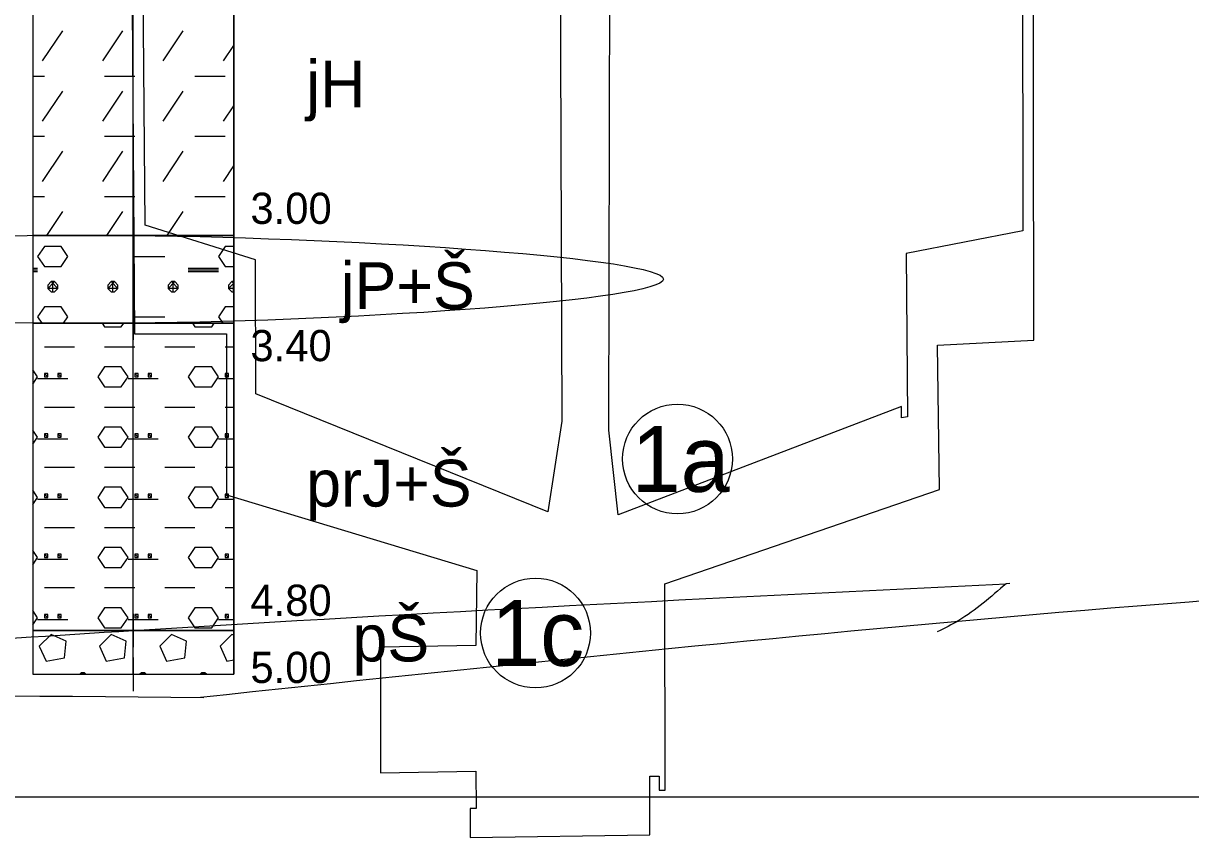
# Model space of a CAD drawing. Extents: x 3042 to 4120, y 576 to 2694.
# Drawn here: x 3468.92 to 3495.5, y 742.77 to 761.32 of the extents above; entities that cross this region are included whole.
import ezdxf

# ---------------------------------------------------------------- set-up
doc = ezdxf.new("R2010")
doc.units = 0
for name, color, linetype in [('18', 7, 'Continuous'), ('51', 7, 'Continuous'), ('52', 7, 'Continuous'), ('53', 7, 'Continuous'), ('56', 7, 'Continuous'), ('nádrže', 7, 'Continuous'), ('rozhraní', 7, 'Continuous')]:
    doc.layers.add(name, color=color, linetype=linetype)

msp = doc.modelspace()

# ---------------------------------------------------------------- linework, layer by layer
at = {"layer": '18'}
for p, q in [((3471.427, 746.491), (3471.427, 771.491)), ((3471.427, 746.872), (3471.427, 746.11)), ((3471.046, 746.491), (3471.808, 746.491))]:
    msp.add_line(p, q, dxfattribs=at)
at = {"layer": '51'}
for p, q in [((3469.363, 760.467), (3469.821, 761.153)), ((3470.735, 760.467), (3471.192, 761.153)), ((3472.107, 760.467), (3472.564, 761.153)), ((3473.478, 760.467), (3473.713, 760.819)), ((3469.141, 760.124), (3469.402, 760.124)), ((3470.773, 760.124), (3471.459, 760.124)), ((3472.831, 760.124), (3473.516, 760.124)), ((3469.363, 759.096), (3469.821, 759.782)), ((3470.735, 759.096), (3471.192, 759.782)), ((3472.107, 759.096), (3472.564, 759.782)), ((3473.478, 759.096), (3473.713, 759.447)), ((3469.141, 758.753), (3469.402, 758.753)), ((3470.773, 758.753), (3471.459, 758.753)), ((3472.831, 758.753), (3473.516, 758.753)), ((3469.363, 757.724), (3469.821, 758.41)), ((3470.735, 757.724), (3471.192, 758.41)), ((3472.107, 757.724), (3472.564, 758.41)), ((3473.478, 757.724), (3473.713, 758.076)), ((3469.141, 757.381), (3469.402, 757.381)), ((3470.773, 757.381), (3471.459, 757.381)), ((3472.831, 757.381), (3473.516, 757.381)), ((3469.456, 756.491), (3469.821, 757.038)), ((3470.827, 756.491), (3471.192, 757.038)), ((3472.199, 756.491), (3472.564, 757.038)), ((3471.459, 756.01), (3472.145, 756.01)), ((3469.141, 755.743), (3469.249, 755.743)), ((3472.678, 755.743), (3473.364, 755.743)), ((3473.516, 755.781), (3473.713, 755.781)), ((3469.141, 755.705), (3469.249, 755.705)), ((3469.141, 755.667), (3469.249, 755.667)), ((3472.678, 755.705), (3473.364, 755.705)), ((3472.678, 755.667), (3473.364, 755.667)), ((3469.592, 755.21), (3469.592, 755.438)), ((3470.964, 755.21), (3470.964, 755.438)), ((3472.335, 755.21), (3472.335, 755.438)), ((3473.707, 755.21), (3473.707, 755.438)), ((3470.719, 754.491), (3470.773, 754.409)), ((3471.459, 754.638), (3472.145, 754.638)), ((3472.776, 754.491), (3472.831, 754.409)), ((3469.402, 753.952), (3470.087, 753.952)), ((3470.773, 753.952), (3471.459, 753.952)), ((3472.145, 753.952), (3472.831, 753.952)), ((3473.516, 753.952), (3473.713, 753.952)), ((3469.249, 753.228), (3469.935, 753.228)), ((3471.307, 753.228), (3471.992, 753.228)), ((3473.364, 753.228), (3473.713, 753.228)), ((3469.402, 752.581), (3470.087, 752.581)), ((3470.773, 752.581), (3471.459, 752.581)), ((3472.145, 752.581), (3472.831, 752.581)), ((3473.516, 752.581), (3473.713, 752.581)), ((3469.249, 751.857), (3469.935, 751.857)), ((3471.307, 751.857), (3471.992, 751.857)), ((3473.364, 751.857), (3473.713, 751.857)), ((3469.402, 751.209), (3470.087, 751.209)), ((3470.773, 751.209), (3471.459, 751.209)), ((3472.145, 751.209), (3472.831, 751.209)), ((3473.516, 751.209), (3473.713, 751.209)), ((3469.249, 750.485), (3469.935, 750.485)), ((3471.307, 750.485), (3471.992, 750.485)), ((3473.364, 750.485), (3473.713, 750.485)), ((3469.402, 749.837), (3470.087, 749.837)), ((3470.773, 749.837), (3471.459, 749.837)), ((3472.145, 749.837), (3472.831, 749.837)), ((3473.516, 749.837), (3473.713, 749.837)), ((3469.249, 749.114), (3469.935, 749.114)), ((3471.307, 749.114), (3471.992, 749.114)), ((3473.364, 749.114), (3473.713, 749.114)), ((3469.402, 748.466), (3470.087, 748.466)), ((3470.773, 748.466), (3471.459, 748.466)), ((3472.145, 748.466), (3472.831, 748.466)), ((3473.516, 748.466), (3473.713, 748.466)), ((3469.249, 747.742), (3469.935, 747.742)), ((3471.307, 747.742), (3471.992, 747.742)), ((3473.364, 747.742), (3473.713, 747.742)), ((3470.24, 746.523), (3470.208, 746.491)), ((3470.278, 746.491), (3470.278, 746.523)), ((3470.284, 746.491), (3470.316, 746.523)), ((3471.611, 746.523), (3471.579, 746.491)), ((3471.649, 746.491), (3471.649, 746.523)), ((3471.656, 746.491), (3471.688, 746.523)), ((3472.983, 746.523), (3472.951, 746.491)), ((3473.021, 746.491), (3473.021, 746.523)), ((3473.027, 746.491), (3473.059, 746.523))]:
    msp.add_line(p, q, dxfattribs=at)
for points in [[(3469.141, 756.491), (3473.713, 756.491), (3473.713, 762.491), (3469.141, 762.491)], [(3469.141, 754.491), (3473.713, 754.491), (3473.713, 756.491), (3469.141, 756.491)], [(3469.141, 747.491), (3473.713, 747.491), (3473.713, 754.491), (3469.141, 754.491)], [(3469.141, 746.491), (3473.713, 746.491), (3473.713, 747.491), (3469.141, 747.491)]]:
    msp.add_lwpolyline(points, close=True, dxfattribs=at)
for points in [[(3469.402, 755.781), (3469.783, 755.781), (3469.935, 756.01), (3469.783, 756.238), (3469.402, 756.238), (3469.249, 756.01), (3469.402, 755.781)], [(3473.713, 756.238), (3473.516, 756.238), (3473.364, 756.01), (3473.516, 755.781)], [(3469.554, 755.438), (3469.478, 755.362), (3469.478, 755.286), (3469.554, 755.21), (3469.63, 755.21), (3469.706, 755.286), (3469.706, 755.362), (3469.63, 755.438), (3469.554, 755.438), (3469.706, 755.286), (3469.478, 755.286), (3469.63, 755.438)], [(3470.926, 755.438), (3470.849, 755.362), (3470.849, 755.286), (3470.926, 755.21), (3471.002, 755.21), (3471.078, 755.286), (3471.078, 755.362), (3471.002, 755.438), (3470.926, 755.438), (3471.078, 755.286), (3470.849, 755.286), (3471.002, 755.438)], [(3472.297, 755.438), (3472.221, 755.362), (3472.221, 755.286), (3472.297, 755.21), (3472.373, 755.21), (3472.45, 755.286), (3472.45, 755.362), (3472.373, 755.438), (3472.297, 755.438), (3472.45, 755.286), (3472.221, 755.286), (3472.373, 755.438)], [(3473.669, 755.438), (3473.593, 755.362), (3473.593, 755.286), (3473.669, 755.21), (3473.713, 755.21)], [(3473.713, 755.286), (3473.593, 755.286), (3473.713, 755.406)], [(3473.713, 755.438), (3473.669, 755.438), (3473.713, 755.394)], [(3469.837, 754.491), (3469.935, 754.638), (3469.783, 754.867), (3469.402, 754.867), (3469.249, 754.638), (3469.347, 754.491)], [(3473.713, 754.867), (3473.516, 754.867), (3473.364, 754.638), (3473.462, 754.491)], [(3470.773, 754.409), (3471.154, 754.409), (3471.208, 754.491)], [(3472.831, 754.409), (3473.212, 754.409), (3473.266, 754.491)], [(3469.141, 753.104), (3469.249, 753.266), (3469.141, 753.429)], [(3469.402, 753.343), (3469.402, 753.266), (3469.478, 753.266), (3469.478, 753.343), (3469.402, 753.343), (3469.478, 753.266)], [(3469.706, 753.343), (3469.706, 753.266), (3469.783, 753.266), (3469.783, 753.343), (3469.706, 753.343), (3469.783, 753.266)], [(3470.773, 753.038), (3471.154, 753.038), (3471.307, 753.266), (3471.154, 753.495), (3470.773, 753.495), (3470.621, 753.266), (3470.773, 753.038)], [(3471.459, 753.343), (3471.459, 753.266), (3471.535, 753.266), (3471.535, 753.343), (3471.459, 753.343), (3471.535, 753.266)], [(3471.764, 753.343), (3471.764, 753.266), (3471.84, 753.266), (3471.84, 753.343), (3471.764, 753.343), (3471.84, 753.266)], [(3472.831, 753.038), (3473.212, 753.038), (3473.364, 753.266), (3473.212, 753.495), (3472.831, 753.495), (3472.678, 753.266), (3472.831, 753.038)], [(3473.516, 753.343), (3473.516, 753.266), (3473.593, 753.266), (3473.593, 753.343), (3473.516, 753.343), (3473.593, 753.266)], [(3469.141, 751.732), (3469.249, 751.895), (3469.141, 752.057)], [(3470.773, 751.666), (3471.154, 751.666), (3471.307, 751.895), (3471.154, 752.123), (3470.773, 752.123), (3470.621, 751.895), (3470.773, 751.666)], [(3472.831, 751.666), (3473.212, 751.666), (3473.364, 751.895), (3473.212, 752.123), (3472.831, 752.123), (3472.678, 751.895), (3472.831, 751.666)], [(3469.402, 751.971), (3469.402, 751.895), (3469.478, 751.895), (3469.478, 751.971), (3469.402, 751.971), (3469.478, 751.895)], [(3469.706, 751.971), (3469.706, 751.895), (3469.783, 751.895), (3469.783, 751.971), (3469.706, 751.971), (3469.783, 751.895)], [(3471.459, 751.971), (3471.459, 751.895), (3471.535, 751.895), (3471.535, 751.971), (3471.459, 751.971), (3471.535, 751.895)], [(3471.764, 751.971), (3471.764, 751.895), (3471.84, 751.895), (3471.84, 751.971), (3471.764, 751.971), (3471.84, 751.895)], [(3473.516, 751.971), (3473.516, 751.895), (3473.593, 751.895), (3473.593, 751.971), (3473.516, 751.971), (3473.593, 751.895)], [(3469.141, 750.361), (3469.249, 750.523), (3469.141, 750.686)], [(3470.773, 750.295), (3471.154, 750.295), (3471.307, 750.523), (3471.154, 750.752), (3470.773, 750.752), (3470.621, 750.523), (3470.773, 750.295)], [(3472.831, 750.295), (3473.212, 750.295), (3473.364, 750.523), (3473.212, 750.752), (3472.831, 750.752), (3472.678, 750.523), (3472.831, 750.295)], [(3469.402, 750.599), (3469.402, 750.523), (3469.478, 750.523), (3469.478, 750.599), (3469.402, 750.599), (3469.478, 750.523)], [(3469.706, 750.599), (3469.706, 750.523), (3469.783, 750.523), (3469.783, 750.599), (3469.706, 750.599), (3469.783, 750.523)], [(3471.459, 750.599), (3471.459, 750.523), (3471.535, 750.523), (3471.535, 750.599), (3471.459, 750.599), (3471.535, 750.523)], [(3471.764, 750.599), (3471.764, 750.523), (3471.84, 750.523), (3471.84, 750.599), (3471.764, 750.599), (3471.84, 750.523)], [(3473.516, 750.599), (3473.516, 750.523), (3473.593, 750.523), (3473.593, 750.599), (3473.516, 750.599), (3473.593, 750.523)], [(3470.773, 748.923), (3471.154, 748.923), (3471.307, 749.152), (3471.154, 749.38), (3470.773, 749.38), (3470.621, 749.152), (3470.773, 748.923)], [(3472.831, 748.923), (3473.212, 748.923), (3473.364, 749.152), (3473.212, 749.38), (3472.831, 749.38), (3472.678, 749.152), (3472.831, 748.923)], [(3469.141, 748.989), (3469.249, 749.152), (3469.141, 749.314)], [(3469.402, 749.228), (3469.402, 749.152), (3469.478, 749.152), (3469.478, 749.228), (3469.402, 749.228), (3469.478, 749.152)], [(3469.706, 749.228), (3469.706, 749.152), (3469.783, 749.152), (3469.783, 749.228), (3469.706, 749.228), (3469.783, 749.152)], [(3471.459, 749.228), (3471.459, 749.152), (3471.535, 749.152), (3471.535, 749.228), (3471.459, 749.228), (3471.535, 749.152)], [(3471.764, 749.228), (3471.764, 749.152), (3471.84, 749.152), (3471.84, 749.228), (3471.764, 749.228), (3471.84, 749.152)], [(3473.516, 749.228), (3473.516, 749.152), (3473.593, 749.152), (3473.593, 749.228), (3473.516, 749.228), (3473.593, 749.152)], [(3470.773, 747.551), (3471.154, 747.551), (3471.307, 747.78), (3471.154, 748.009), (3470.773, 748.009), (3470.621, 747.78), (3470.773, 747.551)], [(3472.831, 747.551), (3473.212, 747.551), (3473.364, 747.78), (3473.212, 748.009), (3472.831, 748.009), (3472.678, 747.78), (3472.831, 747.551)], [(3469.141, 747.617), (3469.249, 747.78), (3469.141, 747.943)], [(3469.402, 747.856), (3469.402, 747.78), (3469.478, 747.78), (3469.478, 747.856), (3469.402, 747.856), (3469.478, 747.78)], [(3469.706, 747.856), (3469.706, 747.78), (3469.783, 747.78), (3469.783, 747.856), (3469.706, 747.856), (3469.783, 747.78)], [(3471.459, 747.856), (3471.459, 747.78), (3471.535, 747.78), (3471.535, 747.856), (3471.459, 747.856), (3471.535, 747.78)], [(3471.764, 747.856), (3471.764, 747.78), (3471.84, 747.78), (3471.84, 747.856), (3471.764, 747.856), (3471.84, 747.78)], [(3473.516, 747.856), (3473.516, 747.78), (3473.593, 747.78), (3473.593, 747.856), (3473.516, 747.856), (3473.593, 747.78)], [(3469.287, 747.132), (3469.44, 746.789), (3469.859, 746.866), (3469.897, 747.247), (3469.554, 747.399), (3469.287, 747.132)], [(3470.659, 747.132), (3470.811, 746.789), (3471.23, 746.866), (3471.268, 747.247), (3470.926, 747.399), (3470.659, 747.132)], [(3472.031, 747.132), (3472.183, 746.789), (3472.602, 746.866), (3472.64, 747.247), (3472.297, 747.399), (3472.031, 747.132)], [(3473.713, 747.38), (3473.669, 747.399), (3473.402, 747.132)], [(3473.402, 747.132), (3473.554, 746.789), (3473.713, 746.818)], [(3470.348, 746.491), (3470.316, 746.523), (3470.24, 746.523), (3470.272, 746.491)], [(3471.72, 746.491), (3471.688, 746.523), (3471.611, 746.523), (3471.643, 746.491)], [(3473.091, 746.491), (3473.059, 746.523), (3472.983, 746.523), (3473.015, 746.491)]]:
    msp.add_lwpolyline(points, dxfattribs=at)
at = {"layer": '53'}
for p, q in [((3469.141, 771.491), (3469.141, 746.491)), ((3473.713, 771.491), (3473.713, 746.491)), ((3469.141, 756.491), (3473.713, 756.491)), ((3469.141, 754.491), (3473.713, 754.491)), ((3469.141, 747.491), (3473.713, 747.491)), ((3469.141, 746.491), (3473.713, 746.491))]:
    msp.add_line(p, q, dxfattribs=at)
at = {"layer": '56'}
for p, q in [((3471.427, 756.872), (3471.427, 756.11)), ((3471.046, 756.491), (3471.808, 756.491)), ((3471.427, 754.872), (3471.427, 754.11)), ((3471.046, 754.491), (3471.808, 754.491)), ((3471.427, 747.872), (3471.427, 747.11)), ((3471.046, 747.491), (3471.808, 747.491)), ((3471.427, 746.872), (3471.427, 746.11)), ((3471.046, 746.491), (3471.808, 746.491))]:
    msp.add_line(p, q, dxfattribs=at)
at = {"layer": 'nádrže'}
for points in [[(3471.348, 769.155), (3471.453, 754.253), (3473.553, 754.253), (3473.553, 750.581), (3479.249, 748.854), (3479.228, 747.145), (3477.053, 747.111), (3477.055, 744.249), (3479.23, 744.282), (3479.231, 743.434), (3479.098, 743.432), (3479.099, 742.769), (3483.193, 742.832), (3483.192, 744.169), (3483.402, 744.172), (3483.402, 743.852), (3483.536, 743.854), (3483.533, 748.549), (3489.784, 750.705), (3489.739, 753.99), (3491.93, 754.103), (3491.912, 770.374)], [(3481.128, 769.093), (3481.187, 752.263), (3480.868, 750.194), (3474.217, 752.879), (3474.206, 755.938), (3471.696, 756.729), (3471.593, 769.293)], [(3491.667, 769.145), (3491.681, 756.593), (3489.025, 756.077), (3489.054, 752.359), (3488.923, 752.334), (3488.921, 752.591), (3482.47, 750.126), (3482.252, 752.056), (3482.297, 769.154)]]:
    msp.add_lwpolyline(points, dxfattribs=at)
at = {"layer": 'rozhraní'}
for p, q in [((3491.386, 748.561), (3491.301, 748.556)), ((3521.114, 743.693), (3424.376, 743.693))]:
    msp.add_line(p, q, dxfattribs=at)
for centre in [(3483.819, 751.398), (3480.586, 747.432)]:
    msp.add_circle(centre, 1.25, dxfattribs=at)
for points in [[(3456.077, 755.397), (3471.427, 756.491), (3483.497, 755.495), (3471.427, 754.491), (3456.952, 755.495)], [(3473.031, 745.954), (3425.231, 746.002), (3379.035, 745.039), (3364.156, 745.104), (3349.279, 745.526), (3319.528, 746.989), (3289.773, 748.528), (3260.007, 749.241), (3246.881, 749.241)], [(3472.958, 745.972), (3510.897, 748.991), (3530.713, 748.991)], [(3450.146, 745.962), (3471.427, 747.491), (3491.301, 748.556)], [(3491.301, 748.556), (3490.222, 747.717), (3489.736, 747.456)]]:
    msp.add_spline(points, degree=3, dxfattribs=at)

# ---------------------------------------------------------------- texts
at = {"layer": '52'}
for s, height, p in [('jH', 1.0668, (3475.364, 759.41)), ('3.00', 0.7112, (3474.094, 756.754)), ('jP+Š', 1.0668, (3476.15, 754.813)), ('3.40', 0.7112, (3474.094, 753.626)), ('prJ+Š', 1.0668, (3475.364, 750.313)), ('4.80', 0.7112, (3474.094, 747.823)), ('pŠ', 1.0668, (3476.419, 746.785)), ('5.00', 0.7112, (3474.094, 746.293))]:
    msp.add_text(s, height=height, dxfattribs=at).set_placement(p)
at = {"layer": 'rozhraní'}
for s, p in [('1a', (3482.775, 750.648)), ('1c', (3479.576, 746.682))]:
    msp.add_text(s, height=1.5, dxfattribs=at).set_placement(p)

doc.saveas('drawing.dxf')
